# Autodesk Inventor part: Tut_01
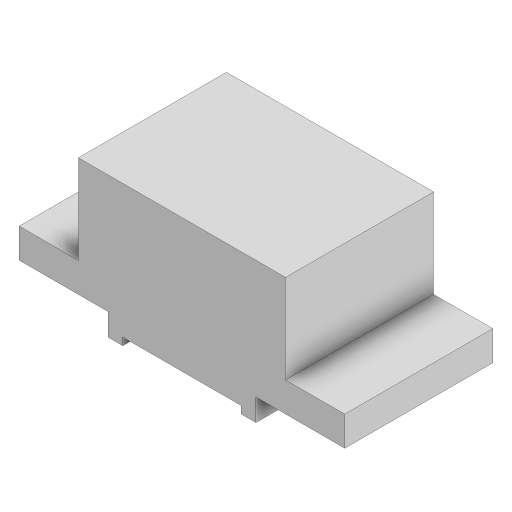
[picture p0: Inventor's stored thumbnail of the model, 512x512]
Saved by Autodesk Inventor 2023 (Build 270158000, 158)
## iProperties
Created: 2022-07
Part Number: Tut_01
Material: Generic
Document SubType Name: Modeling
Designer: LENOVO-CADCIM
Density: 1 g/cm^3
Appearance: Default
Author: LENOVO-CADCIM
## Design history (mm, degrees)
sketch "Sketch1"
  geometry: L1 (0, 0)-(50.8, 0); L2 (50.8, 0)-(50.8, -6.35); L3 (50.8, -6.35)-(63.5, -6.35); L4 (63.5, -6.35)-(63.5, 12.7); L5 (63.5, 12.7)-(139.7, 12.7); L6 (139.7, 12.7)-(139.7, 38.1); L7 (139.7, 38.1)-(88.9, 38.1); L8 (88.9, 38.1)-(88.9, 114.3); L9 (88.9, 114.3)-(-88.9, 114.3); L10 (-88.9, 114.3)-(-88.9, 38.1); L11 (-88.9, 38.1)-(-139.7, 38.1); L12 (-139.7, 38.1)-(-139.7, 12.7); L13 (-139.7, 12.7)-(-63.5, 12.7); L14 (-63.5, 12.7)-(-63.5, -6.35); L15 (-63.5, -6.35)-(-50.8, -6.35); L16 (-50.8, -6.35)-(-50.8, 0); L17 (-50.8, 0)-(0, 0)
  constraints: 34 end point, 12 perpendicular, 2 point on line, 1 horizontal, 1 vertical
  dimensions: "d0" = 50.8 distance of L1.start L1.end; "d1" = 6.35 distance of L1.end L2.end; "d2" = 12.7 distance of L2.end L3.end; "d3" = 19.05 distance of L3.end L4.end; "d4" = 76.2 distance of L4.end L5.end; "d5" = 25.4 distance of L5.end L6.end; "d6" = 50.8 distance of L6.end L7.end; "d7" = 76.2 distance of L7.end L8.end; "d8" = 177.8 distance of L8.end L9.end; "d9" = 76.2 distance of L9.end L10.end; "d10" = 50.8 distance of L10.end L11.end; "d12" = 25.4 distance of L11.end L12.end; "d13" = 76.2 distance of L12.end L13.end; "d14" = 19.05 distance of L13.end L14.end; "d15" = 12.7 distance of L14.end L15.end; "d16" = 6.35 distance of L15.end L16.end; "d17" = 50.8 distance of L16.end L1.start (derived)
extrude "Extrusion1" new body sketch "Sketch1" distance "d18" = 127; taper "d19" = 0 deg
body "Solid1"
